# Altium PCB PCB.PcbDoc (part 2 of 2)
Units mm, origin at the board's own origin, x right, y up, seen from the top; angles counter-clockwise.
Board outline 92.39 x 84.17 mm, 2 copper layers (Top Layer, Bottom Layer); 172 components, 86 nets, 462 pads, 473 vias.
Unrouted connection lines stored in the file: 353.
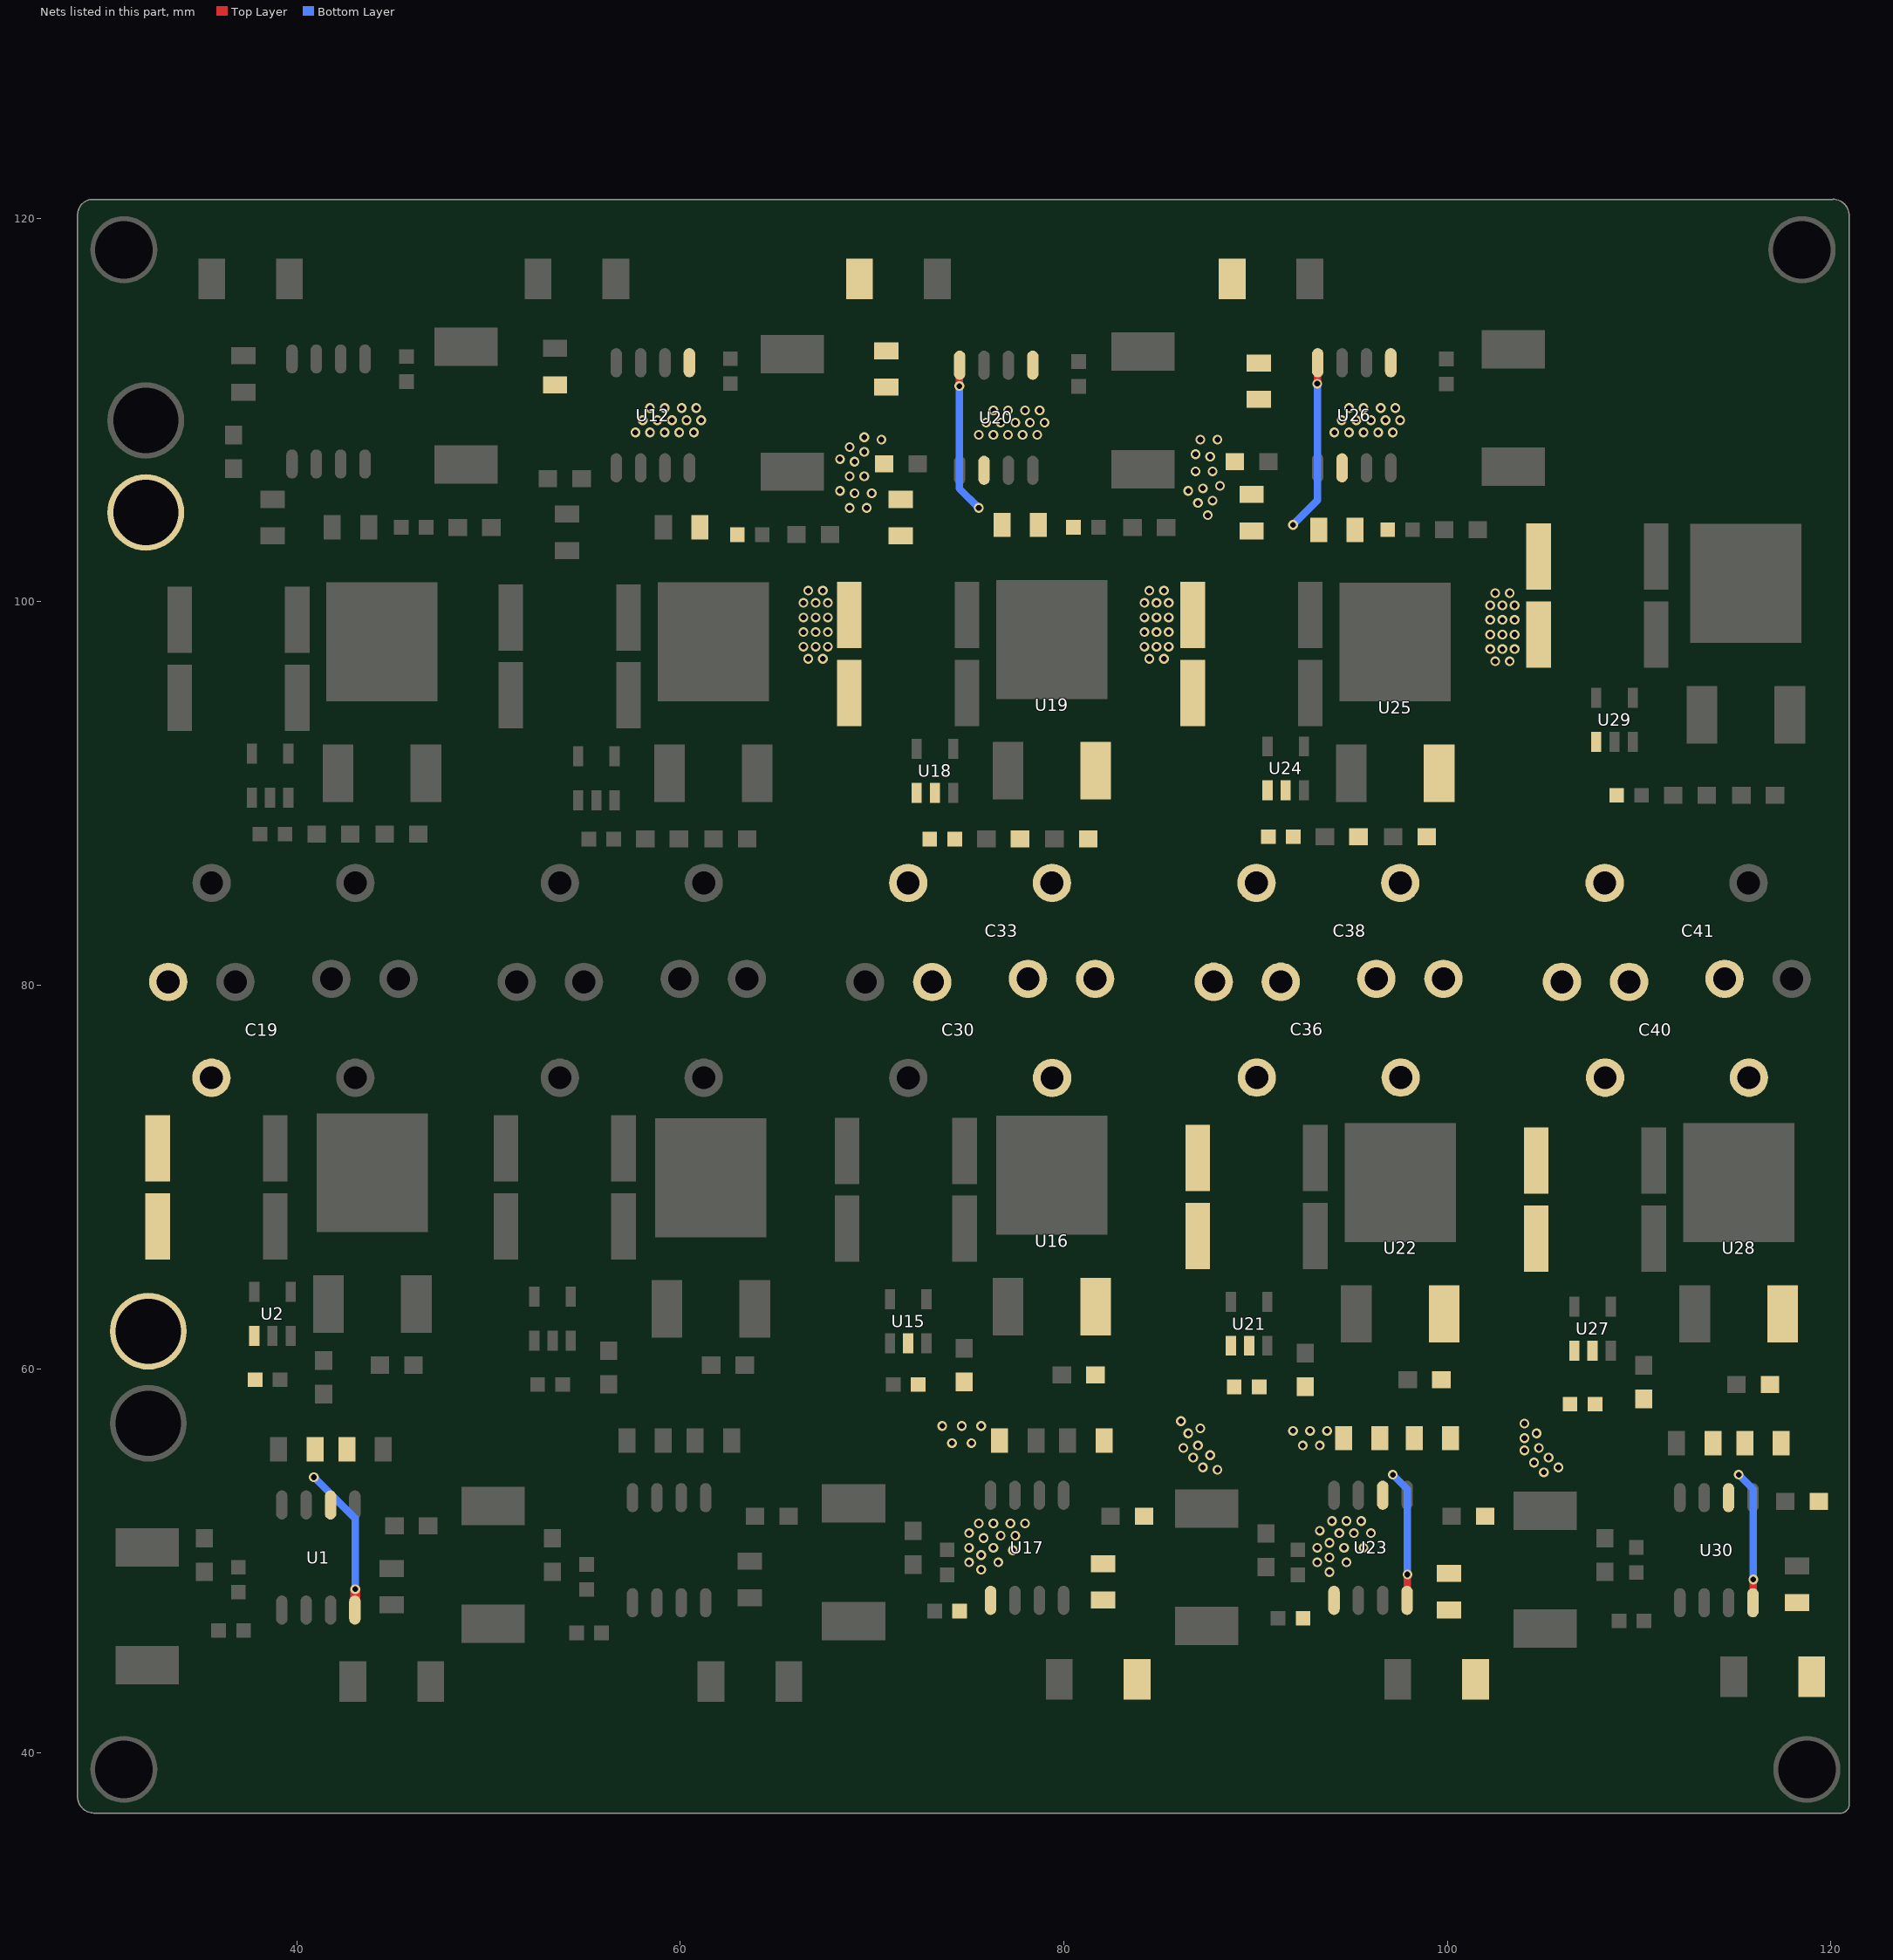
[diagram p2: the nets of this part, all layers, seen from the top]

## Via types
v1: diameter 0.508, hole 0.305, Top Layer to Bottom Layer, 473 vias

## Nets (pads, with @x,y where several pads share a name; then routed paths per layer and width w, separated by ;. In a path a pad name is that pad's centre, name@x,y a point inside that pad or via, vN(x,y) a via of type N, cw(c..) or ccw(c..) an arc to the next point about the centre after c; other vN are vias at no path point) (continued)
P6: C21.1 C25.2 C27.2 C29.2 C30.2 C30.4 C32.2 C33.2 C33.4 C37.1 C39.1 C43.1 C45.1 L5.2 R31.2 R32.1 R35.1 R36.1 R37.2 U12.1 U15.2 U16.3 U18.1 U20.4 U20.6 | length 7.8
  Top Layer w0.381: v1(74.549,111.252) 74.559,111.262 U20.4@74.559,112.258
  Bottom Layer w0.381: v1(74.549,111.252) 74.549,105.918 v1(75.565,104.902)
  other v1: 66.675,97.028 67.437,97.028 66.421,97.663 67.056,97.663 67.691,97.663 66.421,98.425 67.056,98.425 67.691,98.425 66.421,99.187 67.056,99.187 67.691,99.187 66.421,99.949 67.056,99.949 67.691,99.949 66.675,100.584 67.437,100.584 57.658,108.839 58.42,108.839 59.182,108.839 59.944,108.839 60.706,108.839 58.039,109.474 58.801,109.474 59.563,109.474 60.325,109.474 61.087,109.474 58.42,110.109 59.182,110.109 60.071,110.109 60.833,110.109
P7: C31.1 C33.1 C33.3 C35.2 C36.1 C36.3 C37.2 C39.2 C43.2 C46.1 C47.1 C49.1 C51.1 L6.2 R38.2 R39.1 R42.1 R43.1 R44.2 U17.1 U18.2 U19.3 U21.1 U23.4 U23.6 | length 6.9
  Top Layer w0.381: U23.4@97.917,47.879 97.907,47.889 97.907,49.266 v1(97.917,49.276)
  Bottom Layer w0.381: v1(97.155,54.483) 97.917,53.721 v1(97.917,49.276)
  other v1: 75.692,49.53 75.057,49.911 76.581,49.911 75.692,50.292 77.343,50.546 75.057,50.673 76.327,50.673 75.819,51.181 76.708,51.308 77.47,51.308 75.057,51.435 75.565,51.943 76.327,51.943 77.216,51.943 77.978,51.943 88.011,54.737 87.249,54.864 86.741,55.372 87.63,55.499 86.233,55.88 86.995,56.007 74.168,56.134 75.184,56.134 86.487,56.642 87.122,56.896 73.66,57.023 74.676,57.023 75.692,57.023 86.106,57.277 68.834,104.902 69.723,104.902 69.088,105.664 69.977,105.664 68.326,105.791 68.834,106.553 69.596,106.553 69.088,107.315 68.326,107.442 69.596,107.823 68.834,108.077 70.485,108.458 69.596,108.585
P8: C36.2 C36.4 C38.2 C38.4 C42.1 C45.2 C46.2 C47.2 C49.2 C52.1 C53.1 C55.1 C58.1 L7.2 R45.2 R46.1 R48.1 R50.1 R51.2 U20.1 U21.2 U22.3 U24.1 U26.4 U26.6 | length 8.9
  Top Layer w0.381: v1(93.218,111.379) 93.228,111.389 U26.4@93.228,112.385
  Bottom Layer w0.381: v1(91.948,104.013) 93.223,105.288 v1@93.223,111.374
  other v1: 84.455,97.028 85.217,97.028 84.201,97.663 84.836,97.663 85.471,97.663 84.201,98.425 84.836,98.425 85.471,98.425 84.201,99.187 84.836,99.187 85.471,99.187 84.201,99.949 84.836,99.949 85.471,99.949 84.455,100.584 85.217,100.584 75.565,108.712 76.327,108.712 77.089,108.712 77.851,108.712 78.613,108.712 75.946,109.347 76.708,109.347 77.47,109.347 78.232,109.347 78.994,109.347 76.327,109.982 77.089,109.982 77.978,109.982 78.74,109.982
P9: C38.1 C38.3 C40.1 C40.3 C48.1 C51.2 C52.2 C53.2 C55.2 C56.1 C59.1 C62.1 C64.1 L8.2 R52.2 R53.1 R54.1 R56.1 R60.2 U23.1 U24.2 U25.3 U27.1 U30.4 U30.6 | length 6.9
  Top Layer w0.381: U30.4@115.951,47.879 115.941,47.889 115.941,49.012 v1(115.951,49.022)
  Bottom Layer w0.381: v1(115.189,54.483) 115.951,53.721 v1(115.951,49.022)
  other v1: 93.853,49.403 93.218,49.911 94.742,49.911 93.853,50.165 93.218,50.673 94.615,50.673 95.631,50.673 93.853,50.927 94.361,51.435 95.123,51.435 96.012,51.435 93.345,51.562 93.98,52.07 94.742,52.07 95.504,52.07 105.029,54.61 105.791,54.864 104.521,55.118 105.283,55.372 104.013,55.753 104.775,55.88 92.456,56.007 93.345,56.007 104.013,56.388 104.648,56.642 91.948,56.769 92.837,56.769 93.726,56.769 104.013,57.15 87.503,104.521 86.995,105.156 87.757,105.283 86.487,105.791 87.249,105.918 88.138,106.045 86.868,106.807 87.757,106.807 87.63,107.569 86.868,107.696 87.122,108.458 88.011,108.458
P10: C40.2 C40.4 C41.2 C41.4 C54.1 C56.2 C58.2 C59.2 C60.1 C62.2 C65.1 L9.2 R58.2 R59.1 R61.1 R62.1 R67.2 U26.1 U27.2 U28.3 U29.1
  other v1: 102.489,96.901 103.251,96.901 102.235,97.536 102.87,97.536 103.505,97.536 102.235,98.298 102.87,98.298 103.505,98.298 102.235,99.06 102.87,99.06 103.505,99.06 102.235,99.822 102.87,99.822 103.505,99.822 102.489,100.457 103.251,100.457 94.107,108.839 94.869,108.839 95.631,108.839 96.393,108.839 97.155,108.839 94.488,109.474 95.25,109.474 96.012,109.474 96.774,109.474 97.536,109.474 94.869,110.109 95.631,110.109 96.52,110.109 97.282,110.109
PWR: C2.1 C4.1 C6.1 C19.1 C19.3 R3.1 R5.1 U1.4 U1.6 U2.1 U5.2 U8.2 | length 7.8
  Top Layer w0.508: U1.4@43.033,47.425 43.051,47.443 43.051,48.512 v1(43.053,48.514)
  Bottom Layer w0.381: v1(40.894,54.356) 43.053,52.197 v1(43.053,48.514)
pads on no net: U1.7 U2.4 U4.7 U6.4 U9.7 U10.4 U12.7 U13.4 U15.4 U17.7 U18.4 U20.7 U21.4 U23.7 U24.4 U26.7 U27.4 U29.4 U30.7

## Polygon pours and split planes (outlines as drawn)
P8 on Top Layer "Top Layer-P8" (solid, pour order 32): 83 vertices, not listed, extent 77.978,42.042 103.251,107.95
P6 on Top Layer "Top Layer-P6" (solid, pour order 33): 93 vertices, not listed, extent 60.378,42.025 85.598,107.823
NetR35_2 on Top Layer "NETR35_2_L01_P043" (solid, pour order 43): 82.677,101.6 83.312,100.965 83.312,94.615 82.169,93.472 80.391,93.472 80.137,93.218 72.898,93.218 72.009,94.107 72.009,98.99 74.619,101.6
NetR44_1 on Top Layer "NETR44_1_L01_P127" (solid, pour order 127): 74.803,105.918 75.057,106.172 75.057,107.442 74.676,107.823 71.882,107.823 71.755,107.696 71.755,106.683 72.012,106.426 73.787,106.426 74.295,105.918
NetC44_1 on Top Layer "NETC44_1_L01_P135" (solid, pour order 135): 19 vertices, not listed, extent 77.851,103.251 85.979,108.331
P8 on Top Layer "P8_L01_P143" (solid, pour order 143): 22 vertices, not listed, extent 70.104,108.331 79.375,113.157
NetR15_2 on Top Layer "NETR15_2_L01_P048" (solid, pour order 48): 64.262,73.406 55.372,73.406 54.229,72.263 54.229,65.532 55.118,64.643 57.531,64.643 58.293,65.405 63.119,65.405 64.77,67.056 64.77,72.898
GND on Top Layer "Top Layer-GND" (solid, pour order 60): 46 vertices, not listed, extent 106.299,76.2 120.777,120.142
P10 on Top Layer "Top Layer-P10" (solid, pour order 23): 79 vertices, not listed, extent 94.615,42.291 120.65,105.156
P10 on Top Layer "P10_L01_P145" (solid, pour order 145): 20 vertices, not listed, extent 89.535,108.458 98.044,113.284
P6 on Top Layer "P6_L01_P142" (solid, pour order 142): 22 vertices, not listed, extent 52.832,108.458 61.468,113.284
P4 on Top Layer "P4_L01_P141" (solid, pour order 141): 23 vertices, not listed, extent 36.576,108.458 44.577,113.538
NetL8_1 on Top Layer "NETL8_1_L01_P140" (solid, pour order 140): 102.235,111.76 104.902,111.76 105.537,112.395 105.537,115.697 102.616,118.618 92.583,118.618 91.821,117.856 91.821,115.824 92.329,115.316 93.98,115.316 95.25,116.586 100.203,116.586 101.727,115.062 101.727,112.268
NetL6_1 on Top Layer "NETL6_1_L01_P139" (solid, pour order 139): 82.931,111.633 85.344,111.633 85.852,112.141 85.852,116.459 83.566,118.745 73.152,118.745 72.263,117.856 72.263,115.697 72.771,115.189 74.676,115.189 75.946,116.459 81.661,116.459 82.423,115.697 82.423,112.141
NetL4_1 on Top Layer "NETL4_1_L01_P138" (solid, pour order 138): 55.118,115.697 55.626,115.189 57.404,115.189 58.547,116.332 62.865,116.332 64.135,115.062 64.135,111.76 64.516,111.379 67.056,111.379 67.691,112.014 67.691,115.824 64.77,118.745 55.753,118.745 55.118,118.11
NetL2_1 on Top Layer "NETL2_1_L01_P137" (solid, pour order 137): 37.846,118.364 38.481,118.999 48.895,118.999 50.673,117.221 50.673,112.141 50.165,111.633 47.752,111.633 47.117,112.268 47.117,115.316 45.974,116.459 41.656,116.459 40.767,115.57 38.227,115.57 37.846,115.951 37.846,116.459
NetC57_1 on Top Layer "NETC57_1_L01_P136" (solid, pour order 136): 19 vertices, not listed, extent 96.52,103.124 105.537,108.331
NetC23_1 on Top Layer "NETC23_1_L01_P134" (solid, pour order 134): 19 vertices, not listed, extent 59.944,102.997 68.58,108.204
NetC9_1 on Top Layer "NETC9_1_L01_P133" (solid, pour order 133): 19 vertices, not listed, extent 43.053,103.251 50.927,108.712
P9 on Top Layer "P9_L01_P132" (solid, pour order 132): 29 vertices, not listed, extent 86.106,104.14 90.932,118.364
P7 on Top Layer "P7_L01_P130" (solid, pour order 130): 21 vertices, not listed, extent 67.945,104.521 72.136,118.618
NetR60_1 on Top Layer "NETR60_1_L01_P128" (solid, pour order 128): 93.472,106.045 93.726,106.299 93.726,107.696 93.472,107.95 90.17,107.95 90.043,107.823 90.043,106.807 90.17,106.68 92.329,106.68 92.964,106.045
NetR28_1 on Top Layer "NETR28_1_L01_P126" (solid, pour order 126): 54.229,105.791 55.753,105.791 56.134,106.172 56.896,106.172 57.023,106.299 57.023,107.823 56.896,107.95 56.007,107.95 55.499,107.442 54.483,107.442 54.229,107.188
NetC54_2 on Top Layer "NETC54_2_L01_P125" (solid, pour order 125): 97.663,103.378 97.917,103.124 100.33,103.124 100.584,103.378 100.584,104.267 100.33,104.521 97.917,104.521 97.663,104.267
NetC42_2 on Top Layer "NETC42_2_L01_P124" (solid, pour order 124): 81.28,103.505 81.661,103.124 83.947,103.124 84.201,103.378 84.201,104.267 83.947,104.521 81.534,104.521 81.28,104.267
NetC21_2 on Top Layer "NETC21_2_L01_P123" (solid, pour order 123): 63.754,102.997 64.008,102.743 66.421,102.743 66.675,102.997 66.675,103.886 66.421,104.14 64.008,104.14 63.754,103.886
NetC7_2 on Top Layer "NETC7_2_L01_P122" (solid, pour order 122): 46.228,103.505 46.482,103.251 48.895,103.251 49.149,103.505 49.149,104.394 48.895,104.648 46.482,104.648 46.228,104.394
P5 on Top Layer "P5_L01_P121" (solid, pour order 121): 22 vertices, not listed, extent 50.927,103.886 55.118,118.618
P3 on Top Layer "P3_L01_P118" (solid, pour order 118): 26 vertices, not listed, extent 34.29,104.648 39.624,118.491
NetL9_1 on Top Layer "NETL9_1_L01_P115" (solid, pour order 115): 106.68,47.879 107.061,47.498 107.061,44.577 108.204,43.434 112.522,43.434 114.173,45.085 115.824,45.085 116.332,44.577 116.332,41.91 114.808,40.386 105.283,40.386 103.29,42.379 103.29,47.537 103.632,47.879
NetC63_1 on Top Layer "NETC63_1_L01_P114" (solid, pour order 114): 112.649,53.848 112.395,54.102 108.204,54.102 107.95,53.848 103.505,53.848 103.251,53.594 103.251,51.562 104.267,50.546 108.585,50.546 109.22,51.181 109.22,52.07 109.601,52.451 112.395,52.451 112.649,52.705
NetR67_1 on Top Layer "NETR67_1_L01_P113" (solid, pour order 113): 118.11,52.197 118.364,52.451 118.364,53.594 117.729,54.229 115.57,54.229 115.443,54.102 115.443,52.705 115.697,52.451 116.586,52.451 116.84,52.197
GND on Top Layer "GND_L01_P111" (solid, pour order 111): 112.317,55.434 112.509,55.626 112.522,55.626 112.522,56.896 112.141,57.277 109.601,57.277 109.093,56.769 109.093,55.88 109.539,55.434
P9 on Top Layer "P9_L01_P110" (solid, pour order 110): 95.123,55.499 95.377,55.753 95.377,57.023 94.996,57.404 91.948,57.404 91.567,57.023 91.567,56.007 92.075,55.499
NetL7_1 on Top Layer "NETL7_1_L01_P109" (solid, pour order 109): 88.646,48.26 89.281,47.625 89.281,44.704 90.297,43.688 95.25,43.688 96.774,45.212 98.298,45.212 98.806,44.704 98.806,41.91 97.409,40.513 87.249,40.513 85.471,42.291 85.471,47.879 85.852,48.26
NetC50_1 on Top Layer "NETC50_1_L01_P108" (solid, pour order 108): 94.361,52.578 94.615,52.832 94.615,53.975 94.361,54.229 91.821,54.229 91.567,53.975 85.725,53.975 85.471,53.721 85.471,51.435 85.979,50.927 89.916,50.927 90.043,50.8 91.059,50.8 92.837,52.578
NetR51_1 on Top Layer "NETR51_1_L01_P106" (solid, pour order 106): 100.584,51.689 100.965,52.07 100.965,52.959 100.203,53.721 99.695,53.721 99.06,54.356 97.79,54.356 97.409,53.975 97.409,52.832 97.663,52.578 98.552,52.578 99.441,51.689 99.695,51.689
NetR37_1 on Top Layer "NETR37_1_L01_P104" (solid, pour order 104): 79.502,52.832 79.883,52.451 81.28,52.451 81.915,51.816 82.804,51.816 83.058,52.07 83.058,52.959 81.915,54.102 80.645,54.102 80.391,54.356 79.756,54.356 79.502,54.102
P7 on Top Layer "P7_L01_P103" (solid, pour order 103): 77.216,55.626 77.47,55.88 77.47,57.15 76.962,57.658 73.533,57.658 73.025,57.15 73.025,56.007 73.406,55.626 76.327,55.626
NetL5_1 on Top Layer "NETL5_1_L01_P102" (solid, pour order 102): 67.056,47.879 67.564,48.387 67.564,48.514 70.358,48.514 70.866,48.006 70.866,45.466 72.136,44.196 78.105,44.196 79.121,45.212 80.772,45.212 81.28,44.704 81.28,42.037 80.137,40.894 68.961,40.894 67.056,42.799
NetC34_1 on Top Layer "NETC34_1_L01_P101" (solid, pour order 101): 17 vertices, not listed, extent 67.056,50.8 76.708,54.229
P5 on Top Layer "P5_L01_P099" (solid, pour order 99): 57.658,55.626 57.912,55.88 57.912,57.15 57.531,57.531 54.483,57.531 54.102,57.15 54.102,56.642 55.118,55.626 56.769,55.626
NetR21_1 on Top Layer "NETR21_1_L01_P098" (solid, pour order 98): 64.262,51.689 64.516,51.943 64.516,52.959 63.5,53.975 61.722,53.975 61.502,54.195 61.053,54.195 60.833,53.975 60.833,52.578 60.96,52.451 61.976,52.451 62.738,51.689
NetC15_1 on Top Layer "NETC15_1_L01_P097" (solid, pour order 97): 57.658,52.451 57.977,52.77 57.977,53.91 57.658,54.229 48.768,54.229 48.387,53.848 48.387,51.435 48.895,50.927 52.451,50.927 52.832,50.546 53.848,50.546 54.102,50.8 54.102,52.197 54.356,52.451
NetL3_1 on Top Layer "NETL3_1_L01_P096" (solid, pour order 96): 17 vertices, not listed, extent 48.387,40.386 62.865,48.133
P3 on Top Layer "P3_L01_P094" (solid, pour order 94): 39.751,56.388 39.497,56.642 36.703,56.642 36.449,56.388 36.449,55.245 36.703,54.991 39.497,54.991 39.751,55.245
NetL1_1 on Top Layer "NETL1_1_L01_P093" (solid, pour order 93): 17 vertices, not listed, extent 29.718,40.132 44.323,47.117
NetC3_1 on Top Layer "NETC3_1_L01_P092" (solid, pour order 92): 17 vertices, not listed, extent 29.718,48.514 39.878,54.61
NetR4_1 on Top Layer "NETR4_1_L01_P089" (solid, pour order 89): 45.466,51.181 45.72,51.435 45.72,52.451 44.323,53.848 42.926,53.848 42.545,53.467 42.545,52.324 42.926,51.943 43.688,51.943 44.45,51.181
NetC61_2 on Top Layer "NETC61_2_L01_P088" (solid, pour order 88): 109.22,46.482 109.22,48.006 108.712,48.514 108.712,49.911 108.585,50.038 107.823,50.038 107.696,49.911 107.696,48.133 108.458,47.371 108.458,46.482
NetC48_2 on Top Layer "NETC48_2_L01_P087" (solid, pour order 87): 90.043,47.752 90.805,46.99 90.805,46.609 91.44,46.609 91.44,47.879 91.059,48.26 91.059,50.038 90.932,50.165 90.17,50.165 90.043,50.038
NetC31_2 on Top Layer "NETC31_2_L01_P086" (solid, pour order 86): 73.533,46.99 73.533,48.006 72.644,48.895 72.644,50.165 72.517,50.292 71.755,50.292 71.628,50.165 71.628,48.514 72.898,47.244 72.898,46.99
NetC13_2 on Top Layer "NETC13_2_L01_P085" (solid, pour order 85): 54.864,45.847 54.864,46.863 53.848,47.879 53.848,49.784 53.721,49.911 52.832,49.911 52.705,49.784 52.705,47.371 54.229,45.847
NetC1_2 on Top Layer "NETC1_2_L01_P084" (solid, pour order 84): 36.195,45.974 36.195,47.244 35.687,47.752 35.687,49.911 34.671,49.911 34.671,47.371 35.56,46.482 35.56,45.974
GND on Top Layer "GND_L01_P083" (solid, pour order 83): 18 vertices, not listed, extent 109.982,46.355 118.999,52.197
P9 on Top Layer "P9_L01_P082" (solid, pour order 82): 19 vertices, not listed, extent 92.202,46.482 100.838,52.324
P7 on Top Layer "P7_L01_P081" (solid, pour order 81): 76.762,47.298 76.327,46.863 74.295,46.863 74.295,47.879 74.73,48.314 74.73,51.743 75.258,52.271 80.444,52.271 81.993,50.722 82.858,50.722 82.858,49.464 77.531,49.464 76.762,48.695
P5 on Top Layer "P5_L01_P080" (solid, pour order 80): 17 vertices, not listed, extent 55.626,45.72 64.389,52.197
P3 on Top Layer "P3_L01_P079" (solid, pour order 79): 18 vertices, not listed, extent 36.957,45.847 45.847,51.816
NetR7_2 on Top Layer "NETR7_2_L01_P077" (solid, pour order 77): 39.37,61.087 40.64,59.817 42.037,59.817 42.037,61.087 41.656,61.468 40.64,61.468 40.132,61.976 40.132,62.357 39.37,62.357
NetR20_2 on Top Layer "NETR20_2_L01_P076" (solid, pour order 76): 53.975,62.103 53.975,60.833 54.61,60.198 57.15,60.198 57.404,60.452 57.404,61.595 56.896,62.103
NetR32_2 on Top Layer "NETR32_2_L01_P075" (solid, pour order 75): 72.517,61.976 72.517,60.706 73.025,60.198 75.819,60.198 75.946,60.325 75.946,61.341 75.311,61.976
NetR59_2 on Top Layer "NETR59_2_L01_P074" (solid, pour order 74): 108.204,61.595 108.204,60.325 108.839,59.69 111.379,59.69 111.633,59.944 111.633,61.087 111.125,61.595
NetR58_1 on Top Layer "NETR58_1_L01_P073" (solid, pour order 73): 21 vertices, not listed, extent 106.172,58.674 115.697,64.516
NetR46_2 on Top Layer "NETR46_2_L01_P072" (solid, pour order 72): 90.297,61.849 90.297,60.579 90.932,59.944 93.472,59.944 93.726,60.198 93.726,61.341 93.218,61.849
NetR45_1 on Top Layer "NETR45_1_L01_P071" (solid, pour order 71): 21 vertices, not listed, extent 88.265,58.928 98.552,64.643
NetR31_1 on Top Layer "NETR31_1_L01_P070" (solid, pour order 70): 22 vertices, not listed, extent 70.485,59.055 80.518,65.024
NetR19_1 on Top Layer "NETR19_1_L01_P069" (solid, pour order 69): 23 vertices, not listed, extent 52.07,59.563 62.23,65.024
PWR on Top Layer "Top Layer-PWR" (solid, pour order 4): 37 vertices, not listed, extent 29.21,52.07 43.561,83.693
NetR6_1 on Top Layer "NETR6_1_L01_P068" (solid, pour order 68): 24 vertices, not listed, extent 37.338,59.69 44.831,65.024
NetR65_2 on Top Layer "NETR65_2_L01_P061" (solid, pour order 61): 109.22,93.345 110.109,93.345 110.236,93.218 110.236,92.837 112.522,90.551 112.522,89.408 112.395,89.281 111.125,89.281 111.125,90.551 109.601,92.075 109.22,92.075
NetR53_2 on Top Layer "NETR53_2_L01_P067" (solid, pour order 67): 92.075,90.805 92.075,89.535 92.964,88.646 92.964,87.122 94.234,87.122 94.234,88.392 92.964,89.662 92.964,90.805
NetR39_2 on Top Layer "NETR39_2_L01_P065" (solid, pour order 65): 75.311,88.138 75.311,86.995 76.581,86.995 76.581,88.265 74.676,90.17 74.676,90.712 73.787,90.712 73.787,89.408 74.041,89.408
P7 on Top Layer "P7_L01_P037" (solid, pour order 37): 62 vertices, not listed, extent 72.898,52.578 98.933,93.091
NetR27_2 on Top Layer "NETR27_2_L01_P064" (solid, pour order 64): 56.134,89.26 56.875,88.519 57.277,88.519 57.531,88.265 57.531,87.122 57.658,86.995 58.674,86.995 58.801,87.122 58.801,88.519 57.023,90.297 56.134,90.297
NetR64_1 on Top Layer "NETR64_1_L01_P057" (solid, pour order 57): 22 vertices, not listed, extent 107.315,89.281 115.989,95.758
NetR52_1 on Top Layer "NETR52_1_L01_P056" (solid, pour order 56): 22 vertices, not listed, extent 90.17,87.122 97.837,93.151
NetR38_1 on Top Layer "NETR38_1_L01_P055" (solid, pour order 55): 20 vertices, not listed, extent 71.882,87.122 80.01,92.964
P3 on Top Layer "P3_L01_P035" (solid, pour order 35): 62 vertices, not listed, extent 38.183,52.451 61.468,92.964
NetR25_1 on Top Layer "NETR25_1_L01_P054" (solid, pour order 54): 20 vertices, not listed, extent 54.229,87.122 62.259,92.71
NetR12_1 on Top Layer "NETR12_1_L01_P052" (solid, pour order 52): 40.005,106.299 40.259,106.553 40.259,107.95 40.005,108.204 38.989,108.204 37.846,109.347 36.195,109.347 36.195,107.95 37.211,107.95 38.862,106.299 39.243,106.299
NetR54_2 on Top Layer "NETR54_2_L01_P051" (solid, pour order 51): 118.237,66.167 117.856,65.786 116.459,65.786 115.575,64.902 111.955,64.838 111.506,64.389 108.458,64.389 107.696,65.151 107.696,71.247 109.728,73.279 117.856,73.279 118.237,72.898
NetR42_2 on Top Layer "NETR42_2_L01_P050" (solid, pour order 50): 99.187,65.786 98.291,64.89 94.048,64.965 93.472,64.389 91.313,64.389 90.551,65.151 90.551,72.39 91.44,73.279 100.076,73.279 100.711,72.644 100.711,66.421 100.076,65.786
NetR29_2 on Top Layer "NETR29_2_L01_P049" (solid, pour order 49): 81.153,66.294 80.2,65.341 75.882,65.341 75.311,64.77 72.771,64.77 72.263,65.278 72.263,72.136 73.533,73.406 82.296,73.406 82.55,73.152 82.55,66.802 82.042,66.294
NetR3_2 on Top Layer "NETR3_2_L01_P047" (solid, pour order 47): 45.974,66.421 44.831,65.278 40.132,65.278 39.878,65.024 37.338,65.024 36.703,65.659 36.703,72.644 37.592,73.533 46.609,73.533 47.244,72.898 47.244,66.929 46.736,66.421
NetR48_2 on Top Layer "NETR48_2_L01_P046" (solid, pour order 46): 100.711,101.6 101.346,100.965 101.346,94.361 100.457,93.472 98.298,93.472 98.044,93.218 91.313,93.218 90.17,94.361 90.17,99.187 92.583,101.6
NetR61_2 on Top Layer "NETR61_2_L01_P045" (solid, pour order 45): 117.094,106.299 118.999,104.394 118.999,97.536 118.364,96.901 116.967,96.901 116.205,96.139 109.347,96.139 108.712,96.774 108.712,105.41 109.601,106.299
NetR22_2 on Top Layer "NETR22_2_L01_P042" (solid, pour order 42): 64.897,101.473 65.405,100.965 65.405,94.361 64.516,93.472 62.738,93.472 62.357,93.091 56.134,93.091 54.229,94.996 54.229,99.314 56.388,101.473
NetR10_2 on Top Layer "NETR10_2_L01_P041" (solid, pour order 41): 38.227,99.441 37.592,98.806 37.592,94.107 38.735,92.964 44.45,92.964 44.704,93.218 47.498,93.218 48.133,93.853 48.133,100.838 47.625,101.346 39.751,101.346 38.227,99.822
NetR13_1 on Top Layer "NETR13_1_L01_P040" (solid, pour order 40): 20 vertices, not listed, extent 37.211,87.376 45.14,92.837
NetR14_2 on Top Layer "NETR14_2_L01_P039" (solid, pour order 39): 39.189,89.154 39.751,89.154 40.386,88.519 40.386,87.281 41.687,87.281 41.687,88.444 41.613,88.519 41.275,88.519 39.948,89.846 39.948,90.424 39.189,90.424
P9 on Top Layer "P9_L01_P038" (solid, pour order 38): 64 vertices, not listed, extent 91.186,52.451 116.078,93.083
P5 on Top Layer "P5_L01_P036" (solid, pour order 36): 60 vertices, not listed, extent 55.245,52.54 80.772,93.091
P2 on Top Layer "Top Layer-P2" (solid, pour order 15): 85 vertices, not listed, extent 32.639,41.783 49.657,108.077
P4 on Top Layer "Top Layer-P4" (solid, pour order 34): 85 vertices, not listed, extent 43.204,42.037 67.31,107.95
GND on Bottom Layer "Bottom Layer-GND" (solid, pour order 154): 43 vertices, not listed, extent 28.829,47.879 120.396,119.38
P10 on Bottom Layer "P10_L02_P149" (solid, pour order 149): 101.473,97.028 102.108,96.393 103.632,96.393 104.14,96.901 104.14,102.997 98.171,108.966 98.171,109.855 97.536,110.49 94.615,110.49 93.726,109.601 93.726,108.204 96.012,105.918 96.012,105.791 96.139,105.791 101.473,100.457
P8 on Bottom Layer "P8_L02_P148" (solid, pour order 148): 83.312,97.028 83.82,96.52 85.217,96.52 86.106,97.409 86.106,102.616 79.629,109.093 79.629,109.855 78.994,110.49 76.073,110.49 75.057,109.474 75.057,108.331 77.47,105.918 77.47,105.791 77.597,105.791 83.312,100.076
P6 on Bottom Layer "P6_L02_P147" (solid, pour order 147): 65.786,96.901 66.167,96.52 67.818,96.52 68.453,97.155 68.453,102.616 61.722,109.347 61.722,110.236 61.087,110.871 58.166,110.871 57.15,109.855 57.15,108.458 59.563,106.045 59.563,105.918 59.69,105.918 65.786,99.822
P4 on Bottom Layer "P4_L02_P146" (solid, pour order 146): 48.133,96.901 48.641,96.393 50.419,96.393 50.927,96.901 50.927,102.997 44.831,109.093 44.831,109.982 44.196,110.617 41.275,110.617 40.259,109.601 40.259,108.204 42.672,105.791 42.672,105.664 42.799,105.664 48.133,100.33
P9 on Bottom Layer "P9_L02_P131" (solid, pour order 131): 19 vertices, not listed, extent 86.233,73.025 110.236,108.966
P7 on Bottom Layer "P7_L02_P129" (solid, pour order 129): 19 vertices, not listed, extent 67.945,73.025 92.202,108.966
P5 on Bottom Layer "P5_L02_P120" (solid, pour order 120): 19 vertices, not listed, extent 50.8,73.025 74.041,109.601
P3 on Bottom Layer "P3_L02_P117" (solid, pour order 117): 17 vertices, not listed, extent 34.798,73.025 55.753,109.728
P9 on Bottom Layer "P9_L02_P112" (solid, pour order 112): 19 vertices, not listed, extent 91.313,48.895 106.553,57.658
P5 on Bottom Layer "P5_L02_P100" (solid, pour order 100): 19 vertices, not listed, extent 54.102,48.641 70.866,57.658
P7 on Bottom Layer "P7_L02_P105" (solid, pour order 105): 19 vertices, not listed, extent 73.152,49.149 88.646,57.785
P3 on Bottom Layer "P3_L02_P095" (solid, pour order 95): 19 vertices, not listed, extent 36.449,48.26 53.213,57.658
PWR on Bottom Layer "PWR_L02_P001" (solid, pour order 1): 33.955,106.934 34.798,105.975 34.798,101.351 34.098,100.651 34.098,84.139 34.798,83.439 34.798,78.486 37.465,75.819 37.465,74.295 36.83,73.66 30.861,73.66 29.21,75.311 29.21,105.918 30.226,106.934

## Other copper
Bottom Layer:
  pour cut-out: 113.157,81.915 113.538,82.296 115.57,82.296 116.036,81.83 116.036,77.131 117.094,76.073 117.094,74.295 116.205,73.406 115.062,73.406 114.173,74.295 114.173,78.359 113.157,79.375

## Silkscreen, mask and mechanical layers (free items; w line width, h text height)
Bottom Overlay:
  text "HERO2025" at 85.852,101.6 h5.08
  text "20241102" at 63.754,99.06 h3.56
  text "超级电容组" at 101.854,98.552 h3.56
  text "Supercapacitor bank" at 93.218,90.551 h5.08
  text "44F*10     1980J" at 88.138,65.532 h3.56
Mechanical 1:
  lines w0.152: 28.57,120.188 28.57,37.731 ccw(c29.437,37.703) 29.409,36.836 120.442,36.836 ; 28.575,120.142 cw(c29.377,120.186) 29.332,120.988 ; 29.341,120.988 120.108,120.988 ; 120.1,120.997 cw(c120.104,120.154) 120.946,120.158 ; 120.396,36.83 120.441,36.828 ccw(c120.468,37.32) 120.961,37.319 120.953,120.189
